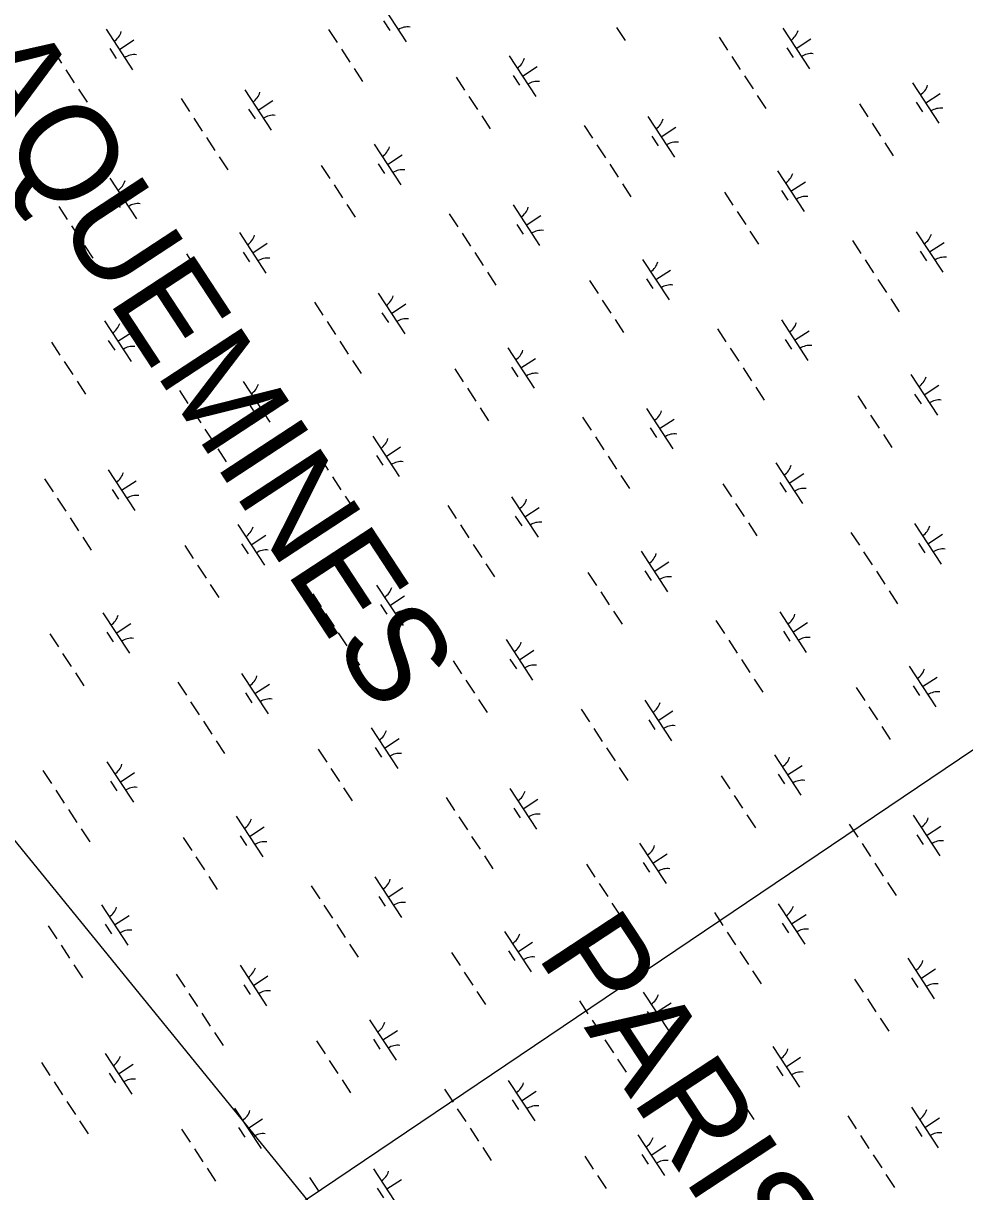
# Model space of a CAD drawing. Extents: x 3945642 to 3966284, y 206476 to 228921.
# Drawn here: x 3960151 to 3961122, y 214912 to 216117 of the extents above; entities that cross this region are included whole.
import ezdxf

# ---------------------------------------------------------------- set-up
doc = ezdxf.new("R2010")
doc.units = 0
for name, color, linetype in [('V-TOPO-GNAM-IDEN', 7, 'Continuous'), ('V-UTIL-LINE', 7, 'Continuous'), ('V-WETL-SWMP', 7, 'Continuous')]:
    doc.layers.add(name, color=color, linetype=linetype)

msp = doc.modelspace()

# ---------------------------------------------------------------- linework, layer by layer
at = {"layer": 'V-UTIL-LINE'}
for points in [[(3960959.9, 211406.8), (3958349.2, 217477.4), (3962483, 212396.3)], [(3961849.2, 215846.1), (3961847.2, 215851.3), (3959391.2, 214194.2)]]:
    msp.add_lwpolyline(points, dxfattribs=at)
at = {"layer": 'V-WETL-SWMP'}
for p, q in [((3960518.3, 216139.8), (3960545.7, 216097.9)), ((3960236.1, 216111.2), (3960263.5, 216069.3)), ((3960522.2, 216119.6), (3960528.8, 216109.6)), ((3960762.6, 216112.7), (3960771.4, 216099.3)), ((3960934.1, 216112.2), (3960961.5, 216070.3)), ((3960249.8, 216090.2), (3960264.8, 216100.1)), ((3960465.6, 216110.6), (3960474.4, 216097.2)), ((3960868.3, 216103), (3960877.1, 216089.6)), ((3960947.8, 216091.2), (3960962.8, 216101.1)), ((3960181.4, 216089.3), (3960190.1, 216075.9)), ((3960240, 216091), (3960246.6, 216081)), ((3960478.8, 216090.5), (3960487.6, 216077.1)), ((3960938, 216092), (3960944.6, 216082)), ((3960651.9, 216083.5), (3960679.3, 216041.7)), ((3960881.4, 216083), (3960890.2, 216069.6)), ((3960194.5, 216069.2), (3960203.3, 216055.9)), ((3960491.9, 216070.4), (3960500.7, 216057)), ((3960655.8, 216063.4), (3960662.4, 216053.4)), ((3960665.6, 216062.6), (3960680.6, 216072.5)), ((3960894.6, 216062.9), (3960903.4, 216049.5)), ((3960597.2, 216061.7), (3960605.9, 216048.3)), ((3961067.7, 216055.9), (3961095.1, 216014.1)), ((3960207.7, 216049.2), (3960216.5, 216035.8)), ((3960313.4, 216039.5), (3960322.1, 216026.1)), ((3960379.1, 216048.6), (3960406.5, 216006.8)), ((3960610.3, 216041.6), (3960619.1, 216028.2)), ((3960907.7, 216042.8), (3960916.5, 216029.4)), ((3961081.4, 216035), (3961096.4, 216044.9)), ((3960383.1, 216028.5), (3960389.7, 216018.5)), ((3960392.8, 216027.7), (3960407.9, 216037.6)), ((3961013, 216034.1), (3961021.7, 216020.7)), ((3961071.6, 216035.8), (3961078.2, 216025.8)), ((3960326.5, 216019.4), (3960335.3, 216006)), ((3960623.5, 216021.6), (3960632.2, 216008.2)), ((3960794.9, 216021), (3960822.3, 215979.2)), ((3960729.1, 216011.9), (3960737.9, 215998.5)), ((3960808.6, 216000.1), (3960823.7, 216010)), ((3961026.1, 216014), (3961034.9, 216000.6)), ((3960339.7, 215999.3), (3960348.4, 215986)), ((3960512.7, 215992.4), (3960540.1, 215950.6)), ((3960742.3, 215991.8), (3960751.1, 215978.4)), ((3960798.9, 216000.9), (3960805.5, 215990.8)), ((3961039.3, 215993.9), (3961048, 215980.6)), ((3960352.8, 215979.3), (3960361.6, 215965.9)), ((3960526.4, 215971.5), (3960541.5, 215981.3)), ((3960458, 215970.6), (3960466.8, 215957.2)), ((3960516.7, 215972.3), (3960523.3, 215962.2)), ((3960755.5, 215971.7), (3960764.2, 215958.3)), ((3960240, 215957.5), (3960267.4, 215915.6)), ((3960928.5, 215964.8), (3960955.9, 215923)), ((3960174.2, 215948.3), (3960183, 215935)), ((3960253.7, 215936.6), (3960268.8, 215946.4)), ((3960471.2, 215950.5), (3960480, 215937.1)), ((3960768.6, 215951.6), (3960777.4, 215938.3)), ((3960873.8, 215942.9), (3960882.6, 215929.6)), ((3960932.5, 215944.7), (3960939.1, 215934.6)), ((3960942.2, 215943.9), (3960957.3, 215953.7)), ((3960244, 215937.3), (3960250.5, 215927.3)), ((3960484.3, 215930.4), (3960493.1, 215917)), ((3960187.4, 215928.3), (3960196.1, 215914.9)), ((3960590, 215920.7), (3960598.8, 215907.3)), ((3960655.8, 215929.8), (3960683.2, 215888)), ((3960669.5, 215908.9), (3960684.6, 215918.8)), ((3960887, 215922.9), (3960895.8, 215909.5)), ((3960200.5, 215908.2), (3960209.3, 215894.8)), ((3960659.8, 215909.7), (3960666.3, 215899.7)), ((3960373.6, 215901.2), (3960401, 215859.4)), ((3960603.2, 215900.6), (3960611.9, 215887.3)), ((3960900.1, 215902.8), (3960908.9, 215889.4)), ((3961071.6, 215902.2), (3961099, 215860.4)), ((3960213.7, 215888.1), (3960222.4, 215874.7)), ((3960387.3, 215880.3), (3960402.3, 215890.2)), ((3961005.8, 215893.1), (3961014.6, 215879.7)), ((3961075.6, 215882.1), (3961082.1, 215872.1)), ((3961085.3, 215881.3), (3961100.4, 215891.2)), ((3960318.9, 215879.4), (3960327.7, 215866)), ((3960377.5, 215881.1), (3960384.1, 215871.1)), ((3960616.3, 215880.6), (3960625.1, 215867.2)), ((3960789.4, 215873.6), (3960816.8, 215831.8)), ((3961019, 215873), (3961027.7, 215859.6)), ((3960332.1, 215859.3), (3960340.8, 215845.9)), ((3960629.5, 215860.5), (3960638.2, 215847.1)), ((3960803.1, 215852.7), (3960818.1, 215862.6)), ((3960734.7, 215851.8), (3960743.5, 215838.4)), ((3960793.3, 215853.5), (3960799.9, 215843.5)), ((3961032.1, 215853), (3961040.9, 215839.6)), ((3960345.2, 215839.3), (3960354, 215825.9)), ((3960516.7, 215838.7), (3960544.1, 215796.9)), ((3960450.9, 215829.6), (3960459.6, 215816.2)), ((3960530.4, 215817.8), (3960545.4, 215827.7)), ((3960747.8, 215831.7), (3960756.6, 215818.3)), ((3961045.3, 215832.9), (3961054, 215819.5)), ((3960234.5, 215810.1), (3960261.9, 215768.3)), ((3960464, 215809.5), (3960472.8, 215796.1)), ((3960520.6, 215818.6), (3960527.2, 215808.5)), ((3960761, 215811.6), (3960769.8, 215798.3)), ((3960932.5, 215811.1), (3960959.9, 215769.3)), ((3960248.2, 215789.2), (3960263.2, 215799)), ((3960866.7, 215802), (3960875.4, 215788.6)), ((3960946.2, 215790.2), (3960961.2, 215800)), ((3960179.8, 215788.3), (3960188.5, 215774.9)), ((3960238.4, 215790), (3960245, 215779.9)), ((3960477.2, 215789.4), (3960485.9, 215776)), ((3960936.4, 215791), (3960943, 215780.9)), ((3960650.3, 215782.5), (3960677.7, 215740.6)), ((3960879.8, 215781.9), (3960888.6, 215768.5)), ((3960192.9, 215768.2), (3960201.7, 215754.8)), ((3960490.3, 215769.3), (3960499.1, 215756)), ((3960654.2, 215762.4), (3960660.8, 215752.3)), ((3960664, 215761.6), (3960679, 215771.4)), ((3960893, 215761.8), (3960901.7, 215748.4)), ((3960595.6, 215760.6), (3960604.3, 215747.3)), ((3961066, 215754.9), (3961093.4, 215713)), ((3960206.1, 215748.1), (3960214.8, 215734.7)), ((3960311.7, 215738.4), (3960320.5, 215725)), ((3960377.5, 215747.5), (3960404.9, 215705.7)), ((3960608.7, 215740.6), (3960617.5, 215727.2)), ((3960906.1, 215741.7), (3960914.9, 215728.3)), ((3961079.7, 215733.9), (3961094.8, 215743.8)), ((3960381.5, 215727.4), (3960388.1, 215717.4)), ((3960391.2, 215726.6), (3960406.3, 215736.5)), ((3961011.4, 215733), (3961020.1, 215719.6)), ((3961070, 215734.7), (3961076.6, 215724.7)), ((3960324.9, 215718.3), (3960333.7, 215705)), ((3960621.9, 215720.5), (3960630.6, 215707.1)), ((3960793.3, 215719.9), (3960820.7, 215678.1)), ((3960727.5, 215710.8), (3960736.3, 215697.4)), ((3960807, 215699), (3960822.1, 215708.9)), ((3961024.5, 215712.9), (3961033.3, 215699.6)), ((3960338, 215698.3), (3960346.8, 215684.9)), ((3960511.1, 215691.3), (3960538.5, 215649.5)), ((3960740.7, 215690.7), (3960749.4, 215677.3)), ((3960797.3, 215699.8), (3960803.9, 215689.8)), ((3961037.7, 215692.9), (3961046.4, 215679.5)), ((3960351.2, 215678.2), (3960360, 215664.8)), ((3960524.8, 215670.4), (3960539.9, 215680.3)), ((3960456.4, 215669.5), (3960465.2, 215656.1)), ((3960515.1, 215671.2), (3960521.6, 215661.2)), ((3960753.8, 215670.7), (3960762.6, 215657.3)), ((3960238.4, 215656.4), (3960265.8, 215614.6)), ((3960926.9, 215663.7), (3960954.3, 215621.9)), ((3960172.6, 215647.3), (3960181.4, 215633.9)), ((3960252.1, 215635.5), (3960267.1, 215645.3)), ((3960469.6, 215649.4), (3960478.3, 215636)), ((3960767, 215650.6), (3960775.8, 215637.2)), ((3960872.2, 215641.9), (3960881, 215628.5)), ((3960930.9, 215643.6), (3960937.4, 215633.5)), ((3960940.6, 215642.8), (3960955.7, 215652.7)), ((3960242.3, 215636.3), (3960248.9, 215626.2)), ((3960482.7, 215629.3), (3960491.5, 215615.9)), ((3960654.2, 215628.8), (3960681.6, 215587)), ((3960185.7, 215627.2), (3960194.5, 215613.8)), ((3960588.4, 215619.7), (3960597.2, 215606.3)), ((3960667.9, 215607.9), (3960682.9, 215617.7)), ((3960885.4, 215621.8), (3960894.1, 215608.4)), ((3960198.9, 215607.1), (3960207.7, 215593.7)), ((3960658.1, 215608.7), (3960664.7, 215598.6)), ((3960372, 215600.2), (3960399.4, 215558.3)), ((3960601.5, 215599.6), (3960610.3, 215586.2)), ((3960898.5, 215601.7), (3960907.3, 215588.3)), ((3961070, 215601.2), (3961097.4, 215559.3)), ((3960212, 215587), (3960220.8, 215573.7)), ((3960385.7, 215579.3), (3960400.7, 215589.1)), ((3961004.2, 215592), (3961013, 215578.7)), ((3961073.9, 215581), (3961080.5, 215571)), ((3961083.7, 215580.3), (3961098.7, 215590.1)), ((3960317.3, 215578.3), (3960326, 215564.9)), ((3960375.9, 215580), (3960382.5, 215570)), ((3960614.7, 215579.5), (3960623.5, 215566.1)), ((3960787.8, 215572.6), (3960815.2, 215530.7)), ((3961017.3, 215572), (3961026.1, 215558.6)), ((3960330.4, 215558.3), (3960339.2, 215544.9)), ((3960627.8, 215559.4), (3960636.6, 215546)), ((3960801.5, 215551.6), (3960816.5, 215561.5)), ((3960733.1, 215550.7), (3960741.8, 215537.3)), ((3960791.7, 215552.4), (3960798.3, 215542.4)), ((3961030.5, 215551.9), (3961039.3, 215538.5)), ((3960343.6, 215538.2), (3960352.4, 215524.8)), ((3960515, 215537.6), (3960542.4, 215495.8)), ((3960449.3, 215528.5), (3960458, 215515.1)), ((3960528.7, 215516.7), (3960543.8, 215526.6)), ((3960746.2, 215530.6), (3960755, 215517.3)), ((3961043.6, 215531.8), (3961052.4, 215518.4)), ((3960232.8, 215509), (3960260.2, 215467.2)), ((3960462.4, 215508.4), (3960471.2, 215495)), ((3960519, 215517.5), (3960525.6, 215507.5)), ((3960759.4, 215510.6), (3960768.2, 215497.2)), ((3960930.8, 215510), (3960958.2, 215468.2)), ((3960246.5, 215488.1), (3960261.6, 215498)), ((3960865.1, 215500.9), (3960873.8, 215487.5)), ((3960944.5, 215489.1), (3960959.6, 215499)), ((3960178.1, 215487.2), (3960186.9, 215473.8)), ((3960236.8, 215488.9), (3960243.4, 215478.9)), ((3960475.6, 215488.4), (3960484.3, 215475)), ((3960934.8, 215489.9), (3960941.4, 215479.9)), ((3960648.6, 215481.4), (3960676, 215439.6)), ((3960878.2, 215480.8), (3960887, 215467.4)), ((3960191.3, 215467.1), (3960200.1, 215453.7)), ((3960488.7, 215468.3), (3960497.5, 215454.9)), ((3960652.6, 215461.3), (3960659.2, 215451.2)), ((3960662.3, 215460.5), (3960677.4, 215470.4)), ((3960891.4, 215460.7), (3960900.1, 215447.4)), ((3960593.9, 215459.6), (3960602.7, 215446.2)), ((3961064.4, 215453.8), (3961091.8, 215412)), ((3960204.4, 215447), (3960213.2, 215433.6)), ((3960310.1, 215437.4), (3960318.9, 215424)), ((3960375.9, 215446.5), (3960403.3, 215404.7)), ((3960607.1, 215439.5), (3960615.9, 215426.1)), ((3960904.5, 215440.7), (3960913.3, 215427.3)), ((3961078.1, 215432.9), (3961093.2, 215442.7)), ((3960379.9, 215426.4), (3960386.4, 215416.3)), ((3960389.6, 215425.6), (3960404.7, 215435.4)), ((3961009.7, 215431.9), (3961018.5, 215418.6)), ((3961068.4, 215433.7), (3961075, 215423.6)), ((3960323.3, 215417.3), (3960332, 215403.9)), ((3960620.2, 215419.4), (3960629, 215406)), ((3960791.7, 215418.9), (3960819.1, 215377)), ((3961022.9, 215411.9), (3961031.7, 215398.5)), ((3960725.9, 215409.7), (3960734.7, 215396.4)), ((3960805.4, 215397.9), (3960820.5, 215407.8)), ((3960336.4, 215397.2), (3960345.2, 215383.8)), ((3960509.5, 215390.3), (3960536.9, 215348.4)), ((3960739.1, 215389.7), (3960747.8, 215376.3)), ((3960795.7, 215398.7), (3960802.2, 215388.7)), ((3961036, 215391.8), (3961044.8, 215378.4)), ((3960349.6, 215377.1), (3960358.3, 215363.7)), ((3960523.2, 215369.3), (3960538.3, 215379.2)), ((3960454.8, 215368.4), (3960463.6, 215355)), ((3960513.5, 215370.1), (3960520, 215360.1)), ((3960752.2, 215369.6), (3960761, 215356.2)), ((3960236.8, 215355.3), (3960264.2, 215313.5)), ((3960925.3, 215362.6), (3960952.7, 215320.8)), ((3960939, 215341.7), (3960954, 215351.6)), ((3960171, 215346.2), (3960179.7, 215332.8)), ((3960250.5, 215334.4), (3960265.5, 215344.3)), ((3960468, 215348.3), (3960476.7, 215335)), ((3960765.4, 215349.5), (3960774.1, 215336.1)), ((3960870.6, 215340.8), (3960879.4, 215327.4)), ((3960929.2, 215342.5), (3960935.8, 215332.5)), ((3960240.7, 215335.2), (3960247.3, 215325.2)), ((3960481.1, 215328.3), (3960489.9, 215314.9)), ((3960652.6, 215327.7), (3960680, 215285.9)), ((3960184.1, 215326.1), (3960192.9, 215312.7)), ((3960586.8, 215318.6), (3960595.5, 215305.2)), ((3960666.3, 215306.8), (3960681.3, 215316.7)), ((3960883.8, 215320.7), (3960892.5, 215307.3)), ((3960197.3, 215306), (3960206, 215292.7)), ((3960656.5, 215307.6), (3960663.1, 215297.5)), ((3960370.4, 215299.1), (3960397.8, 215257.3)), ((3960599.9, 215298.5), (3960608.7, 215285.1)), ((3960896.9, 215300.6), (3960905.7, 215287.3)), ((3961068.4, 215300.1), (3961095.8, 215258.3)), ((3960210.4, 215286), (3960219.2, 215272.6)), ((3960384.1, 215278.2), (3960399.1, 215288.1)), ((3961002.6, 215291), (3961011.3, 215277.6)), ((3961072.3, 215280), (3961078.9, 215269.9)), ((3961082.1, 215279.2), (3961097.1, 215289)), ((3960315.7, 215277.3), (3960324.4, 215263.9)), ((3960374.3, 215279), (3960380.9, 215268.9)), ((3960613.1, 215278.4), (3960621.8, 215265)), ((3960786.2, 215271.5), (3960813.6, 215229.7)), ((3961015.7, 215270.9), (3961024.5, 215257.5)), ((3960328.8, 215257.2), (3960337.6, 215243.8)), ((3960626.2, 215258.4), (3960635, 215245)), ((3960799.9, 215250.6), (3960814.9, 215260.4)), ((3960731.5, 215249.6), (3960740.2, 215236.3)), ((3960790.1, 215251.4), (3960796.7, 215241.3)), ((3961028.9, 215250.8), (3961037.6, 215237.4)), ((3960342, 215237.1), (3960350.7, 215223.7)), ((3960513.4, 215236.6), (3960540.8, 215194.7)), ((3960447.6, 215227.4), (3960456.4, 215214)), ((3960527.1, 215215.6), (3960542.2, 215225.5)), ((3960744.6, 215229.6), (3960753.4, 215216.2)), ((3961042, 215230.7), (3961050.8, 215217.4)), ((3960231.2, 215207.9), (3960258.6, 215166.1)), ((3960460.8, 215207.4), (3960469.6, 215194)), ((3960517.4, 215216.4), (3960524, 215206.4)), ((3960757.8, 215209.5), (3960766.5, 215196.1)), ((3960929.2, 215208.9), (3960956.6, 215167.1)), ((3960244.9, 215187), (3960260, 215196.9)), ((3960863.4, 215199.8), (3960872.2, 215186.4)), ((3960942.9, 215188), (3960958, 215197.9)), ((3960176.5, 215186.1), (3960185.3, 215172.7)), ((3960235.2, 215187.8), (3960241.7, 215177.8)), ((3960473.9, 215187.3), (3960482.7, 215173.9)), ((3960933.2, 215188.8), (3960939.8, 215178.8)), ((3960647, 215180.3), (3960674.4, 215138.5)), ((3960876.6, 215179.7), (3960885.4, 215166.4)), ((3960189.7, 215166), (3960198.4, 215152.7)), ((3960487.1, 215167.2), (3960495.9, 215153.8)), ((3960651, 215160.2), (3960657.5, 215150.2)), ((3960660.7, 215159.4), (3960675.8, 215169.3)), ((3960889.7, 215159.7), (3960898.5, 215146.3)), ((3960592.3, 215158.5), (3960601.1, 215145.1)), ((3961062.8, 215152.7), (3961090.2, 215110.9)), ((3960202.8, 215146), (3960211.6, 215132.6)), ((3960308.5, 215136.3), (3960317.3, 215122.9)), ((3960374.3, 215145.4), (3960401.7, 215103.6)), ((3960605.5, 215138.4), (3960614.2, 215125)), ((3960902.9, 215139.6), (3960911.7, 215126.2)), ((3961076.5, 215131.8), (3961091.6, 215141.7)), ((3960378.2, 215125.3), (3960384.8, 215115.2)), ((3960388, 215124.5), (3960403, 215134.4)), ((3961008.1, 215130.9), (3961016.9, 215117.5)), ((3961066.8, 215132.6), (3961073.3, 215122.6)), ((3960321.6, 215116.2), (3960330.4, 215102.8)), ((3960618.6, 215118.3), (3960627.4, 215105)), ((3960790.1, 215117.8), (3960817.5, 215076)), ((3961021.3, 215110.8), (3961030, 215097.4)), ((3960724.3, 215108.7), (3960733.1, 215095.3)), ((3960803.8, 215096.9), (3960818.8, 215106.7)), ((3960334.8, 215096.1), (3960343.6, 215082.7)), ((3960507.9, 215089.2), (3960535.3, 215047.4)), ((3960737.4, 215088.6), (3960746.2, 215075.2)), ((3960794, 215097.7), (3960800.6, 215087.6)), ((3961034.4, 215090.7), (3961043.2, 215077.3)), ((3960348, 215076.1), (3960356.7, 215062.7)), ((3960521.6, 215068.3), (3960536.6, 215078.1)), ((3960453.2, 215067.3), (3960462, 215054)), ((3960511.8, 215069.1), (3960518.4, 215059)), ((3960750.6, 215068.5), (3960759.4, 215055.1)), ((3960235.2, 215054.3), (3960262.6, 215012.4)), ((3960923.7, 215061.6), (3960951.1, 215019.7)), ((3960937.4, 215040.7), (3960952.4, 215050.5)), ((3960169.4, 215045.1), (3960178.1, 215031.7)), ((3960248.9, 215033.3), (3960263.9, 215043.2)), ((3960466.3, 215047.3), (3960475.1, 215033.9)), ((3960763.7, 215048.4), (3960772.5, 215035.1)), ((3960869, 215039.7), (3960877.7, 215026.3)), ((3960927.6, 215041.4), (3960934.2, 215031.4)), ((3960239.1, 215034.1), (3960245.7, 215024.1)), ((3960479.5, 215027.2), (3960488.3, 215013.8)), ((3960650.9, 215026.6), (3960678.3, 214984.8)), ((3960182.5, 215025.1), (3960191.3, 215011.7)), ((3960585.2, 215017.5), (3960593.9, 215004.1)), ((3960664.6, 215005.7), (3960679.7, 215015.6)), ((3960882.1, 215019.7), (3960890.9, 215006.3)), ((3960195.7, 215005), (3960204.4, 214991.6)), ((3960654.9, 215006.5), (3960661.5, 214996.5)), ((3960368.7, 214998), (3960396.1, 214956.2)), ((3960598.3, 214997.4), (3960607.1, 214984.1)), ((3960895.3, 214999.6), (3960904.1, 214986.2)), ((3961001, 214989.9), (3961009.7, 214976.5)), ((3961066.7, 214999), (3961094.1, 214957.2)), ((3960208.8, 214984.9), (3960217.6, 214971.5)), ((3960372.7, 214977.9), (3960379.3, 214967.9)), ((3960382.4, 214977.1), (3960397.5, 214987)), ((3961070.7, 214978.9), (3961077.3, 214968.9)), ((3961080.4, 214978.1), (3961095.5, 214988)), ((3960314, 214976.2), (3960322.8, 214962.8)), ((3960611.5, 214977.4), (3960620.2, 214964)), ((3960784.5, 214970.4), (3960811.9, 214928.6)), ((3961014.1, 214969.8), (3961022.9, 214956.4)), ((3960327.2, 214956.1), (3960336, 214942.7)), ((3960624.6, 214957.3), (3960633.4, 214943.9)), ((3960798.2, 214949.5), (3960813.3, 214959.4)), ((3960729.8, 214948.6), (3960738.6, 214935.2)), ((3960788.5, 214950.3), (3960795.1, 214940.3)), ((3961027.3, 214949.7), (3961036, 214936.4)), ((3960340.3, 214936), (3960349.1, 214922.7)), ((3960511.8, 214935.5), (3960539.2, 214893.7)), ((3961040.4, 214929.7), (3961049.2, 214916.3)), ((3960446, 214926.4), (3960454.8, 214913)), ((3960525.5, 214914.6), (3960540.6, 214924.4)), ((3960743, 214928.5), (3960751.8, 214915.1)), ((3960515.8, 214915.4), (3960522.3, 214905.3))]:
    msp.add_line(p, q, dxfattribs=at)
for centre, start, end in [((3960547.3, 216095.9), 82.4574, 124.0011), ((3960234.8, 216113.5), 302.4575, 344.0011), ((3960932.8, 216114.5), 302.4575, 344.0011), ((3960265.1, 216067.3), 82.4574, 124.0011), ((3960650.6, 216085.9), 302.4575, 344.0011), ((3960963.1, 216068.3), 82.4574, 124.0011), ((3960680.9, 216039.7), 82.4574, 124.0011), ((3961066.4, 216058.2), 302.4575, 344.0011), ((3960377.9, 216050.9), 302.4575, 344.0011), ((3961096.7, 216012), 82.4574, 124.0011), ((3960408.2, 216004.7), 82.4574, 124.0011), ((3960793.7, 216023.3), 302.4575, 344.0011), ((3960824, 215977.1), 82.4574, 124.0011), ((3960511.5, 215994.7), 302.4575, 344.0011), ((3960541.8, 215948.5), 82.4574, 124.0011), ((3960238.8, 215959.8), 302.4575, 344.0011), ((3960927.3, 215967.1), 302.4575, 344.0011), ((3960269, 215913.6), 82.4574, 124.0011), ((3960957.6, 215920.9), 82.4574, 124.0011), ((3960654.6, 215932.2), 302.4575, 344.0011), ((3960372.4, 215903.6), 302.4575, 344.0011), ((3960684.8, 215886), 82.4574, 124.0011), ((3961070.4, 215904.6), 302.4575, 344.0011), ((3960402.6, 215857.4), 82.4574, 124.0011), ((3960788.2, 215875.9), 302.4575, 344.0011), ((3961100.6, 215858.3), 82.4574, 124.0011), ((3960818.4, 215829.7), 82.4574, 124.0011), ((3960515.4, 215841), 302.4575, 344.0011), ((3960545.7, 215794.8), 82.4574, 124.0011), ((3960233.2, 215812.4), 302.4575, 344.0011), ((3960931.2, 215813.4), 302.4575, 344.0011), ((3960263.5, 215766.2), 82.4574, 124.0011), ((3960649, 215784.8), 302.4575, 344.0011), ((3960961.5, 215767.2), 82.4574, 124.0011), ((3960679.3, 215738.6), 82.4574, 124.0011), ((3961064.8, 215757.2), 302.4575, 344.0011), ((3960376.3, 215749.9), 302.4575, 344.0011), ((3961095.1, 215711), 82.4574, 124.0011), ((3960406.6, 215703.7), 82.4574, 124.0011), ((3960792.1, 215722.3), 302.4575, 344.0011), ((3960822.4, 215676), 82.4574, 124.0011), ((3960509.9, 215693.6), 302.4575, 344.0011), ((3960540.1, 215647.4), 82.4574, 124.0011), ((3960237.1, 215658.7), 302.4575, 344.0011), ((3960925.7, 215666), 302.4575, 344.0011), ((3960267.4, 215612.5), 82.4574, 124.0011), ((3960955.9, 215619.8), 82.4574, 124.0011), ((3960652.9, 215631.1), 302.4575, 344.0011), ((3960370.7, 215602.5), 302.4575, 344.0011), ((3960683.2, 215584.9), 82.4574, 124.0011), ((3961068.7, 215603.5), 302.4575, 344.0011), ((3960401, 215556.3), 82.4574, 124.0011), ((3960786.5, 215574.9), 302.4575, 344.0011), ((3961099, 215557.3), 82.4574, 124.0011), ((3960816.8, 215528.7), 82.4574, 124.0011), ((3960513.8, 215540), 302.4575, 344.0011), ((3960544.1, 215493.7), 82.4574, 124.0011), ((3960231.6, 215511.3), 302.4575, 344.0011), ((3960929.6, 215512.3), 302.4575, 344.0011), ((3960261.9, 215465.1), 82.4574, 124.0011), ((3960647.4, 215483.7), 302.4575, 344.0011), ((3960959.9, 215466.1), 82.4574, 124.0011), ((3960677.7, 215437.5), 82.4574, 124.0011), ((3961063.2, 215456.1), 302.4575, 344.0011), ((3960374.7, 215448.8), 302.4575, 344.0011), ((3961093.5, 215409.9), 82.4574, 124.0011), ((3960404.9, 215402.6), 82.4574, 124.0011), ((3960790.5, 215421.2), 302.4575, 344.0011), ((3960508.3, 215392.6), 302.4575, 344.0011), ((3960820.7, 215375), 82.4574, 124.0011), ((3960538.5, 215346.4), 82.4574, 124.0011), ((3960235.5, 215357.6), 302.4575, 344.0011), ((3960924.1, 215365), 302.4575, 344.0011), ((3960265.8, 215311.4), 82.4574, 124.0011), ((3960954.3, 215318.7), 82.4574, 124.0011), ((3960651.3, 215330), 302.4575, 344.0011), ((3960369.1, 215301.4), 302.4575, 344.0011), ((3960681.6, 215283.8), 82.4574, 124.0011), ((3961067.1, 215302.4), 302.4575, 344.0011), ((3960399.4, 215255.2), 82.4574, 124.0011), ((3960784.9, 215273.8), 302.4575, 344.0011), ((3961097.4, 215256.2), 82.4574, 124.0011), ((3960815.2, 215227.6), 82.4574, 124.0011), ((3960512.2, 215238.9), 302.4575, 344.0011), ((3960542.5, 215192.7), 82.4574, 124.0011), ((3960230, 215210.3), 302.4575, 344.0011), ((3960928, 215211.3), 302.4575, 344.0011), ((3960260.3, 215164.1), 82.4574, 124.0011), ((3960645.8, 215182.7), 302.4575, 344.0011), ((3960958.3, 215165.1), 82.4574, 124.0011), ((3960676, 215136.4), 82.4574, 124.0011), ((3961061.6, 215155), 302.4575, 344.0011), ((3960373.1, 215147.7), 302.4575, 344.0011), ((3961091.8, 215108.8), 82.4574, 124.0011), ((3960403.3, 215101.5), 82.4574, 124.0011), ((3960788.8, 215120.1), 302.4575, 344.0011), ((3960506.6, 215091.5), 302.4575, 344.0011), ((3960819.1, 215073.9), 82.4574, 124.0011), ((3960536.9, 215045.3), 82.4574, 124.0011), ((3960233.9, 215056.6), 302.4575, 344.0011), ((3960922.4, 215063.9), 302.4575, 344.0011), ((3960264.2, 215010.4), 82.4574, 124.0011), ((3960952.7, 215017.7), 82.4574, 124.0011), ((3960649.7, 215029), 302.4575, 344.0011), ((3960367.5, 215000.4), 302.4575, 344.0011), ((3960680, 214982.8), 82.4574, 124.0011), ((3961065.5, 215001.3), 302.4575, 344.0011), ((3960397.8, 214954.1), 82.4574, 124.0011), ((3960783.3, 214972.7), 302.4575, 344.0011), ((3961095.8, 214955.1), 82.4574, 124.0011), ((3960813.6, 214926.5), 82.4574, 124.0011), ((3960510.6, 214937.8), 302.4575, 344.0011)]:
    msp.add_arc(centre, 17.6, start, end, dxfattribs=at)

# ---------------------------------------------------------------- texts
at = {"layer": 'V-TOPO-GNAM-IDEN'}
for s, rotation, p in [('PLAQUEMINES', 303.2489, (3959988.6, 216210.6)), ('PARISH,', 303.3489, (3960679.4, 215155.8))]:
    msp.add_text(s, height=100, rotation=rotation, dxfattribs=at).set_placement(p)

doc.saveas('drawing.dxf')
